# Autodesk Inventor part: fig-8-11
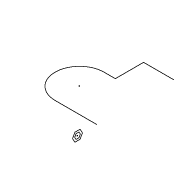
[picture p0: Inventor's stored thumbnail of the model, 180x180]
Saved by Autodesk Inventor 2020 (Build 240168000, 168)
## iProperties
Created: 2004-05
Part Number: fig-8-11
Document SubType Name: Modeling
Designer: CADCIM Technologies
Manufacturer: Standard
Standards Organization: Custom
Density: 1 g/cm^3
Material: Generic
Appearance: Default
Author: CADCIM Technologies
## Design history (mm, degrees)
sketch "Sketch1"
  geometry: L1 (-42.583, 3.219)-(-90.066, 3.219); L2 (-90.066, 58.92)-(-77.282, 58.92); L3 (-77.282, 58.92)-(-77.282, 91.063); L4 (-77.282, 91.063)-(-42.583, 91.063); A1 r 27.851 centre (-90.066, 31.07) between (-90.066, 58.92) and (-90.066, 3.219)
  constraints: 8 end point, 2 parallel, 2 point on circle, 2 tangent, 1 centre point, 1 perpendicular
workplane "Work Plane2"
body "Solid1"
sketch "Sketch2"
  geometry: L1 (16.303, 0)-(19.151, 4.934); L2 (19.151, 4.934)-(24.849, 4.934); L3 (24.849, 4.934)-(27.697, 0); L4 (27.697, 0)-(24.849, -4.934); L5 (24.849, -4.934)-(19.151, -4.934); L6 (19.151, -4.934)-(16.303, 0); L7 (18.744, 0)-(20.372, 2.819); L8 (20.372, 2.819)-(23.628, 2.819); L9 (23.628, 2.819)-(25.256, 0); L10 (25.256, 0)-(23.628, -2.819); L11 (23.628, -2.819)-(20.372, -2.819); L12 (20.372, -2.819)-(18.744, 0); 2 further points
  constraints: 24 end point, 1 coincident, 22 other
